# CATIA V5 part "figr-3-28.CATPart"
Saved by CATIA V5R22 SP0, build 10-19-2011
Part number: Part1
Bounding box of the stored display mesh (mm): x 0 to 71.72, y -62.404 to 71.526, z 0 to 0
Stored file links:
  D:\Gaurav_V\CATIA V5-6R2012_manuscript\Gaurav_Catia\CATIA-V5-6R2012\catia_v5-6r2012_Prts\c03_catia_v5-6r2012_prt\figr-3-28.CATPart
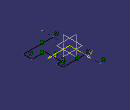
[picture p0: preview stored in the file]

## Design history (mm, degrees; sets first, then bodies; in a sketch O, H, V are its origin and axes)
Body1 (main body)
  Sketch1 on xy-plane, origin (0, 0, 0), H (1, 0, 0), V (0, 1, 0)
    axis line L1 (0, 71.5261) -> (1.8602, -62.4039)
    point P1 (0, 71.5261)
    line L2 (0.4896, 36.2738) -> (51.465, 36.2738)
    point P3 (0.4896, 36.2738)
    line L3 (51.465, 36.2738) -> (51.465, 23.0127)
    line L4 (51.465, 23.0127) -> (41.544, 23.0127)
    line L5 (41.544, 23.0127) -> (41.544, -16.3784)
    line L6 (41.544, -16.3784) -> (71.7203, -16.3784)
    line L7 (71.7203, -16.3784) -> (71.7203, -36.696)
    line L8 (71.7203, -36.696) -> (1.5031, -36.696)
    point P10 (1.5031, -36.696)
    coincidence: P1 V, P3 L1, P10 L1
    horizontal: L2 H, L4 H, L6 H, L8 H
    vertical: L3 V, L5 V, L7 V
